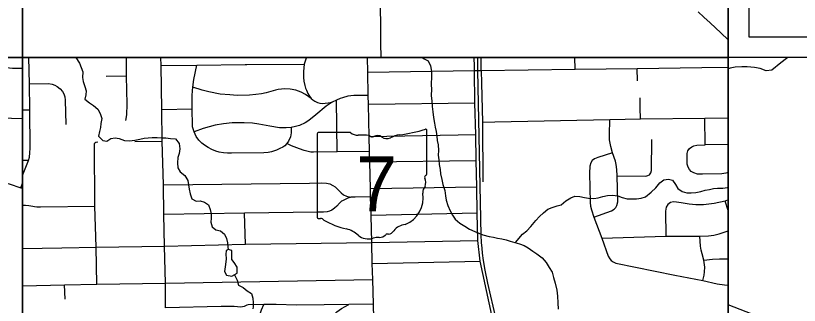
# Model space of a CAD drawing. Extents: x 25.6 to 80.6, y 0.2 to 24.5.
# Drawn here: x 40.98 to 44.756, y 16.537 to 17.932 of the extents above; entities that cross this region are included whole.
import ezdxf

# ---------------------------------------------------------------- set-up
doc = ezdxf.new("R2010")
doc.units = 0
for name, color, linetype in [('GM_X_County_Road', 7, 'Continuous'), ('GM_X_Minor_Lake', 7, 'Continuous'), ('GM_X_Minor_River', 7, 'Continuous'), ('GM_X_Rail_Line', 7, 'Continuous'), ('GM_X_State_Route', 7, 'Continuous'), ('GM_X_State_Shield', 7, 'Continuous'), ('GM_X_Township_Road', 7, 'Continuous'), ('SH_Data', 7, 'Continuous'), ('SH_Text', 7, 'Continuous')]:
    doc.layers.add(name, color=color, linetype=linetype)

msp = doc.modelspace()

# ---------------------------------------------------------------- linework, layer by layer
at = {"layer": 'GM_X_County_Road'}
for p, q in [((43.19, 17.6872), (43.1891, 17.7303)), ((43.223, 17.6682), (43.2221, 17.7303)), ((43.223, 17.6682), (43.2245, 17.6061)), ((41.702, 16.5259), (41.7012, 16.6437))]:
    msp.add_line(p, q, dxfattribs=at)
for points in [[(41.0128, 17.1618), (41.0327, 17.2096), (41.0418, 17.2352), (41.0459, 17.2505), (41.0486, 17.2706), (41.0503, 17.2942), (41.048, 17.4781), (41.0465, 17.6038), (41.0441, 17.7303)], [(41.7012, 16.6437), (41.6971, 16.8224), (41.6944, 16.9752), (41.6922, 17.1167), (41.6865, 17.3277), (41.685, 17.4787), (41.681, 17.6918), (41.6801, 17.7303)], [(43.4744, 15.6231), (43.4157, 15.8771), (43.3295, 16.2378), (43.2913, 16.4079), (43.2182, 16.7492), (43.2068, 16.8496), (43.2038, 16.9808), (43.2018, 17.1076), (43.1983, 17.2332), (43.1967, 17.3603), (43.1924, 17.511), (43.1904, 17.6677), (43.19, 17.6872)], [(43.2245, 17.6061), (43.2289, 17.4196), (43.2882, 17.4207)], [(43.2882, 17.4207), (43.842, 17.4314), (43.991, 17.4346), (44.3, 17.4385), (44.4128, 17.4405)]]:
    msp.add_lwpolyline(points, dxfattribs=at)
at = {"layer": 'GM_X_Minor_Lake'}
for points in [[(42.0209, 16.8011), (42.0034, 16.8054), (41.9936, 16.7992), (41.9931, 16.784), (41.995, 16.7605), (41.9916, 16.7331), (41.986, 16.7004), (41.9961, 16.6823), (42.0212, 16.6781), (42.0468, 16.6914), (42.0479, 16.7202), (42.0331, 16.7428), (42.0208, 16.7571)], [(42.0208, 16.7571), (42.0209, 16.8011)]]:
    msp.add_lwpolyline(points, dxfattribs=at)
at = {"layer": 'GM_X_Minor_River'}
for points in [[(41.2693, 17.7303), (41.2696, 17.7298), (41.2874, 17.7028), (41.296, 17.6824), (41.3039, 17.6605), (41.3021, 17.6339), (41.3054, 17.6142), (41.3126, 17.59), (41.319, 17.5696), (41.3177, 17.5506), (41.3128, 17.5292), (41.335, 17.5113), (41.3549, 17.4987), (41.3764, 17.4808), (41.3865, 17.4604), (41.3945, 17.437), (41.3903, 17.4119), (41.3891, 17.3929), (41.3841, 17.3738), (41.3799, 17.3517), (41.3999, 17.3315), (41.4196, 17.3272), (41.4391, 17.3404), (41.4588, 17.3437), (41.4793, 17.341), (41.5037, 17.3299), (41.528, 17.3288), (41.5537, 17.3322), (41.5778, 17.3378), (41.599, 17.3427), (41.6187, 17.3429), (41.6383, 17.3447), (41.6611, 17.3458), (41.6823, 17.3431), (41.7028, 17.3441), (41.7255, 17.3407), (41.7498, 17.338), (41.7683, 17.3162), (41.7702, 17.2912), (41.7676, 17.2676), (41.7618, 17.2485), (41.7599, 17.2227), (41.7618, 17.1999), (41.7727, 17.1796), (41.7957, 17.1624), (41.8089, 17.1383), (41.813, 17.1171), (41.8164, 17.0959), (41.8205, 17.0732), (41.8284, 17.0498), (41.8491, 17.0379), (41.8695, 17.0397), (41.8893, 17.0331), (41.9092, 17.0213), (41.9171, 16.9986), (41.922, 16.9782), (41.9215, 16.9561), (41.9211, 16.9371), (41.926, 16.9152), (41.9451, 16.901), (41.9664, 16.896), (41.9863, 16.8804), (41.9958, 16.8585), (42.0006, 16.838), (42.0017, 16.8175), (42.0038, 16.8053)], [(42.9386, 17.7303), (42.948, 17.7246), (42.967, 17.715), (42.978, 17.6894), (42.983, 17.6636), (42.9833, 17.6408), (42.9825, 17.5983), (42.9828, 17.5778), (42.9817, 17.5466), (42.9844, 17.5194), (42.9871, 17.4943), (42.9897, 17.4685), (42.9939, 17.4413), (42.9974, 17.4147), (43.0007, 17.3943), (43.0063, 17.3746), (43.0089, 17.3511), (43.0115, 17.3299), (43.0149, 17.3094), (43.0168, 17.2829), (43.0164, 17.2608), (43.019, 17.2381), (43.0208, 17.2153), (43.025, 17.1903), (43.0268, 17.1706), (43.0333, 17.1434), (43.0382, 17.1191), (43.0477, 17.0904), (43.0504, 17.0646), (43.0545, 17.0427), (43.0625, 17.017), (43.0727, 16.992), (43.0844, 16.9709), (43.0983, 16.9514), (43.1206, 16.9335), (43.1443, 16.9179), (43.1672, 16.9037), (43.1916, 16.8927), (43.2313, 16.8765), (43.2617, 16.8686), (43.2815, 16.8651), (43.302, 16.8601), (43.3225, 16.8566), (43.343, 16.8523), (43.3628, 16.8465), (43.3856, 16.84), (43.407, 16.8327), (43.4306, 16.8246), (43.4497, 16.8135), (43.4719, 16.7986), (43.491, 16.7845), (43.5171, 16.7666), (43.5356, 16.7426), (43.5511, 16.7192), (43.5651, 16.6974), (43.5715, 16.6717), (43.5788, 16.6437), (43.5876, 16.6096), (43.5903, 16.5808), (43.5916, 16.5497), (43.5935, 16.5186)], [(44.7004, 17.7303), (44.6933, 17.7249), (44.667, 17.704)], [(44.667, 17.704), (44.6235, 17.67), (44.5955, 17.6667), (44.5673, 17.677), (44.5399, 17.6821), (44.5042, 17.6855), (44.4784, 17.6852), (44.4465, 17.6834), (44.423, 17.6793), (44.4128, 17.675)], [(43.3887, 16.8389), (43.4222, 16.88), (43.4424, 16.8954), (43.4618, 16.9162), (43.4856, 16.9454), (43.5042, 16.9654), (43.5237, 16.9831), (43.5446, 16.9994), (43.5657, 17.0088), (43.5891, 17.0159), (43.6087, 17.0215), (43.6311, 17.0401), (43.6544, 17.0541), (43.674, 17.0627), (43.699, 17.0608), (43.7203, 17.0557), (43.74, 17.053), (43.7651, 17.051), (43.787, 17.0544), (43.8096, 17.0608), (43.8323, 17.0664), (43.855, 17.0675), (43.8808, 17.064), (43.9014, 17.0567), (43.9265, 17.0502), (43.95, 17.0506), (43.9719, 17.0501), (43.9939, 17.0535), (44.015, 17.0598), (44.0427, 17.0815), (44.0643, 17.103), (44.0829, 17.1276), (44.1024, 17.1408), (44.1258, 17.1449), (44.1448, 17.1399), (44.1588, 17.1195), (44.1697, 17.0999), (44.1919, 17.0851), (44.214, 17.0793), (44.2344, 17.0781), (44.2579, 17.0807), (44.2805, 17.0855), (44.3024, 17.0919), (44.3228, 17.0952), (44.3425, 17.0993), (44.3621, 17.1019), (44.3871, 17.1014), (44.4098, 17.1048), (44.4128, 17.1059)], [(42.0339, 16.6847), (42.0465, 16.6587), (42.0537, 16.6345), (42.0758, 16.6234), (42.095, 16.6077), (42.1157, 16.5936), (42.1221, 16.5724), (42.1239, 16.5497), (42.1242, 16.5307), (42.1235, 16.5202)]]:
    msp.add_lwpolyline(points, dxfattribs=at)
at = {"layer": 'GM_X_Rail_Line'}
for points in [[(43.2951, 16.4705), (43.2554, 16.6435), (43.2415, 16.7067), (43.2337, 16.7535), (43.2295, 16.7885), (43.2269, 16.8128), (43.2251, 16.8392), (43.2235, 16.875), (43.2073, 17.6679), (43.2061, 17.7303)], [(47.8128, 15.8191), (47.6057, 15.8302), (47.3402, 15.8521), (47.1631, 15.8871), (46.9912, 15.9223), (46.7273, 15.9853), (45.9383, 16.1769), (45.6136, 16.2567), (45.5036, 16.2842), (45.3992, 16.2924), (45.0499, 16.3176), (44.9789, 16.3252), (44.6728, 16.4383), (44.4128, 16.5397)]]:
    msp.add_lwpolyline(points, dxfattribs=at)
at = {"layer": 'GM_X_State_Route'}
for points in [[(42.7406, 17.7303), (42.7405, 17.7348), (42.7396, 17.7946), (42.7387, 17.8812), (42.7378, 17.976), (42.7363, 18.0903), (42.7345, 18.1848), (42.7325, 18.3068), (42.7307, 18.3811), (42.7294, 18.4657), (42.7275, 18.534), (42.7248, 18.6943), (42.7233, 18.8161), (42.7222, 18.8744), (42.7208, 18.9664), (42.7195, 19.0521), (42.7188, 19.0882), (42.7177, 19.1628), (42.716, 19.2796), (42.7133, 19.4075), (42.7128, 19.4303)], [(44.2691, 17.9501), (44.2962, 17.9245), (44.3264, 17.8967), (44.377, 17.8489), (44.4128, 17.815)], [(42.707, 16.4054), (42.7033, 16.5436), (42.7004, 16.6623), (42.6982, 16.7393), (42.696, 16.8392), (42.6925, 16.9703), (42.69, 17.0594), (42.69, 17.1003), (42.6863, 17.2266), (42.6854, 17.2779), (42.6831, 17.3503), (42.6794, 17.5033), (42.6785, 17.5479), (42.6774, 17.6597), (42.6758, 17.7303)]]:
    msp.add_lwpolyline(points, dxfattribs=at)
at = {"layer": 'GM_X_State_Shield'}
for p, q in [((42.5929, 17.3692), (42.4384, 17.3692)), ((42.9606, 17.1697), (42.9606, 17.3791)), ((42.4332, 17.3623), (42.4332, 16.962)), ((42.9605, 17.1698), (42.9606, 17.1697))]:
    msp.add_line(p, q, dxfattribs=at)
for centre, radius, start, end in [((42.4393, 17.3631), 0.00611, 98.1301, 188.1301), ((42.6296, 17.4156), 0.0593, 231.6195, 271.1119), ((42.7727, 17.9148), 0.5592, 275.8445, 288.9065), ((42.9547, 17.3799), 0.00587, 351.8621, 97.738), ((42.6493, 17.1445), 0.2127, 80.4867, 94.9883), ((42.6976, 17.3652), 0.0171, 219.7921, 297.1024), ((42.7227, 17.3189), 0.0355, 54.4667, 119.1411), ((42.7685, 17.3824), 0.0428, 233.8562, 294.8282), ((42.8441, 17.2469), 0.1125, 97.3462, 120.7689), ((42.9592, 17.1543), 0.00909, 107.944, 210.337), ((42.9014, 17.1279), 0.0545, 340.033, 23.6496), ((42.9543, 17.1689), 0.00628, 289.6038, 7.7341), ((42.9816, 17.0821), 0.0397, 136.8065, 186.9296), ((42.8041, 17.0554), 0.1399, 292.3089, 8.9858), ((42.4393, 16.9611), 0.00616, 171.9584, 258.3066), ((42.4403, 17.0021), 0.047, 267.339, 280.6039), ((42.4499, 16.9389), 0.017, 29.7484, 93.2717), ((42.664, 17.2985), 0.4038, 240.4129, 257.1985), ((42.863, 16.8497), 0.0766, 94.4031, 142.5768), ((42.5436, 16.7822), 0.1264, 47.1842, 75.836), ((42.7711, 16.8682), 0.012, 65.7517, 132.6484), ((42.766, 16.9232), 0.0452, 282.8732, 323.2771), ((42.6803, 16.9369), 0.0802, 230.7004, 286.2918), ((42.7266, 16.7986), 0.0659, 85.6951, 111.2099), ((42.7325, 16.907), 0.0427, 268.777, 315.5493)]:
    msp.add_arc(centre, radius, start, end, dxfattribs=at)
at = {"layer": 'GM_X_Township_Road'}
for p, q in [((43.6758, 17.6744), (43.6747, 17.7303)), ((42.0938, 17.6968), (42.3702, 17.6981)), ((43.9768, 17.6184), (43.975, 17.677)), ((41.512, 17.6403), (41.4165, 17.6391)), ((42.6774, 17.6597), (43.1904, 17.6677)), ((43.1904, 17.6677), (43.223, 17.6682)), ((42.529, 17.2759), (42.5257, 17.5253)), ((41.8303, 17.4819), (41.685, 17.4787)), ((43.1924, 17.511), (42.6794, 17.5033)), ((41.0128, 17.4776), (41.048, 17.4781)), ((40.9067, 17.44), (41.0128, 17.4372)), ((43.2289, 17.4196), (43.2301, 17.1323)), ((44.3013, 17.3102), (44.3, 17.4385)), ((42.6831, 17.3503), (43.1967, 17.3603)), ((41.5543, 17.3252), (41.6865, 17.3277)), ((44.4128, 17.311), (44.3013, 17.3102)), ((41.0418, 17.2352), (41.0128, 17.2349)), ((43.1983, 17.2332), (42.6863, 17.2266)), ((41.0055, 17.1036), (41.0128, 17.1251)), ((41.6922, 17.1167), (42.3952, 17.1255)), ((42.69, 17.1003), (43.2018, 17.1076)), ((44.4128, 16.9944), (44.3983, 17.0393)), ((42.0866, 16.8309), (42.0826, 16.9803)), ((43.2038, 16.9808), (42.6925, 16.9703)), ((42.696, 16.8392), (43.2068, 16.8496)), ((41.0128, 16.8105), (41.2022, 16.8138)), ((42.6982, 16.7393), (43.2182, 16.7492)), ((41.0128, 16.6999), (41.0124, 16.6988)), ((41.218, 16.5664), (41.2157, 16.6354))]:
    msp.add_line(p, q, dxfattribs=at)
for points in [[(41.5127, 17.7303), (41.512, 17.7253), (41.512, 17.6403), (41.515, 17.5061), (41.5133, 17.455), (41.5097, 17.4275)], [(42.3808, 17.7303), (42.3779, 17.7216), (42.3702, 17.6981), (42.3661, 17.6625), (42.3672, 17.6335), (42.3686, 17.6168), (42.3729, 17.5958), (42.3769, 17.5825), (42.3806, 17.5737), (42.3879, 17.5572), (42.3959, 17.5435), (42.4039, 17.5334), (42.4116, 17.5265), (42.4213, 17.5194), (42.4338, 17.5133), (42.4448, 17.5105), (42.4585, 17.5093), (42.4719, 17.5103), (42.4863, 17.5123), (42.5043, 17.516)], [(40.892, 17.6871), (40.964, 17.6791), (41.0128, 17.6793)], [(41.681, 17.6918), (41.8526, 17.6932), (42.0859, 17.6968), (42.0938, 17.6968)], [(42.2365, 17.2848), (42.2272, 17.2808), (42.2127, 17.2765), (42.1965, 17.2735), (42.1759, 17.2714), (42.0193, 17.2696), (42.0003, 17.2702), (41.9811, 17.2714), (41.9609, 17.2743), (41.9443, 17.2787), (41.9246, 17.287), (41.9072, 17.2962), (41.8892, 17.3075), (41.8762, 17.3177), (41.8621, 17.3325), (41.8494, 17.3506), (41.8401, 17.3731), (41.8354, 17.3863), (41.8325, 17.3958), (41.8316, 17.4043), (41.8303, 17.4819), (41.8307, 17.5468), (41.8322, 17.5703), (41.8333, 17.587), (41.838, 17.6245), (41.8526, 17.6932)], [(43.223, 17.6682), (43.6758, 17.6744), (43.975, 17.677), (44.286, 17.6817), (44.4128, 17.6835)], [(41.0465, 17.6038), (41.138, 17.6043), (41.1551, 17.602), (41.1683, 17.5974), (41.1803, 17.5907), (41.1942, 17.5798), (41.205, 17.5673), (41.2115, 17.5548), (41.2168, 17.5403), (41.2191, 17.5255), (41.221, 17.4083)], [(42.4039, 17.5334), (42.3762, 17.552), (42.3561, 17.5627), (42.3298, 17.5725), (42.3031, 17.5777), (42.2775, 17.579), (42.2608, 17.5784), (42.2455, 17.5764), (42.2315, 17.5731), (42.2089, 17.5658), (42.1865, 17.5602), (42.1642, 17.555), (42.137, 17.5514), (42.106, 17.549), (42.0466, 17.5481), (42.0123, 17.55), (41.966, 17.5545), (41.9112, 17.5644), (41.8782, 17.5735), (41.8333, 17.587)], [(42.6785, 17.5479), (42.6086, 17.5471), (42.5811, 17.5437), (42.5546, 17.5369), (42.543, 17.5327), (42.5257, 17.5253), (42.5043, 17.516), (42.4899, 17.506)], [(43.991, 17.4346), (43.9884, 17.4886), (43.9895, 17.5364)], [(42.4899, 17.506), (42.4755, 17.496), (42.4258, 17.455), (42.3922, 17.4277), (42.3745, 17.4157), (42.3468, 17.4031), (42.3282, 17.3974), (42.3077, 17.3929), (42.2828, 17.3909), (42.2506, 17.3921), (42.2042, 17.3998), (42.1522, 17.41), (42.1215, 17.4141), (42.0813, 17.4163), (42.0237, 17.4153), (41.9817, 17.4114), (41.9412, 17.4045), (41.8829, 17.388), (41.8401, 17.3731)], [(43.7656, 16.9615), (43.85, 16.9922), (43.8631, 16.9997), (43.8712, 17.0084), (43.8772, 17.0178), (43.8806, 17.0353), (43.8779, 17.16), (43.8769, 17.191), (43.8737, 17.2144), (43.8694, 17.2307), (43.8551, 17.2707), (43.8468, 17.3022), (43.8417, 17.3339), (43.8417, 17.3582), (43.842, 17.4314)], [(42.3077, 17.3929), (42.3069, 17.3681), (42.3036, 17.3489), (42.295, 17.3274), (42.2871, 17.3155), (42.2764, 17.305), (42.268, 17.2992), (42.2533, 17.2918), (42.2365, 17.2848)], [(43.8779, 17.16), (44.0161, 17.1594), (44.0264, 17.1617), (44.0344, 17.1662), (44.0407, 17.1745), (44.0441, 17.1865), (44.045, 17.3354)], [(41.3704, 16.6393), (41.3682, 16.8168), (41.3621, 17.0145), (41.3596, 17.316), (41.3613, 17.3201), (41.3662, 17.3233), (41.3762, 17.3245)], [(42.6854, 17.2779), (42.529, 17.2759), (42.4148, 17.2742), (42.4015, 17.2753), (42.3828, 17.2792), (42.3701, 17.2828), (42.3478, 17.2898), (42.309, 17.3053), (42.2871, 17.3155)], [(44.4128, 17.1767), (44.4023, 17.1738), (44.3826, 17.1704), (44.2891, 17.1679), (44.265, 17.1682), (44.2471, 17.1743), (44.2347, 17.1822), (44.2263, 17.1914), (44.2202, 17.2018), (44.2157, 17.2163), (44.2153, 17.268), (44.2193, 17.2804), (44.2261, 17.2921), (44.2374, 17.301), (44.248, 17.3057), (44.2627, 17.3089), (44.3013, 17.3102)], [(43.8551, 17.2707), (43.7842, 17.2482), (43.7696, 17.2422), (43.7582, 17.2339), (43.7513, 17.2233), (43.7468, 17.207), (43.7453, 17.1741), (43.7486, 17.032), (43.7503, 17.0148), (43.7541, 16.9972), (43.7656, 16.9615), (43.8047, 16.8604), (43.8347, 16.7731), (43.8421, 16.7609), (43.849, 16.7526), (43.8589, 16.746), (43.8724, 16.7405), (44.1556, 16.6829), (44.2907, 16.6562), (44.3596, 16.6413), (44.395, 16.6357), (44.4128, 16.6339)], [(39.8547, 17.2112), (39.8666, 17.1932), (39.9331, 17.1796), (40.0798, 17.1537), (40.1385, 17.1475), (40.2033, 17.1464), (40.4013, 17.1396), (40.5305, 17.1362), (40.5559, 17.1345), (40.5812, 17.1294), (40.6032, 17.1238), (40.6935, 17.1204), (40.7155, 17.1215), (40.7538, 17.1193), (40.7753, 17.1199), (40.7916, 17.1244), (40.8085, 17.1311), (40.8255, 17.1334), (40.8954, 17.1306), (40.9185, 17.1294), (40.9491, 17.1225), (41.0055, 17.1036), (41.0128, 17.101)], [(42.3952, 17.1255), (42.4514, 17.1262), (42.4784, 17.1252), (42.494, 17.1214), (42.5079, 17.1143), (42.519, 17.1072), (42.5315, 17.0945), (42.5485, 17.0781), (42.56, 17.0691), (42.5746, 17.063), (42.5946, 17.0586)], [(42.5542, 17.0402), (42.5506, 17.0383), (42.5408, 17.0294), (42.5274, 17.015), (42.5167, 17.0045), (42.5031, 16.9958), (42.4915, 16.991), (42.4806, 16.9878), (42.4635, 16.9859), (42.4349, 16.9853), (42.0826, 16.9803), (41.6944, 16.9752)], [(42.69, 17.0594), (42.6157, 17.0578), (42.5946, 17.0586), (42.5798, 17.0536), (42.5542, 17.0402)], [(44.4128, 17.0447), (44.3983, 17.0393), (44.3457, 17.0273), (44.2936, 17.0207), (44.2579, 17.0204), (44.2256, 17.0241), (44.1864, 17.0301), (44.1635, 17.0344), (44.1495, 17.0356), (44.1346, 17.0321), (44.1215, 17.023), (44.1135, 17.009), (44.1109, 16.9912), (44.1118, 16.8694)], [(41.0128, 17.0198), (41.0269, 17.0198), (41.0441, 17.0181), (41.0625, 17.014), (41.0712, 17.0124), (41.0823, 17.012), (41.1003, 17.0117), (41.3621, 17.0145)], [(43.8047, 16.8604), (44.1118, 16.8694), (44.2756, 16.8694), (44.3188, 16.8717), (44.3442, 16.8754), (44.3688, 16.8814), (44.4128, 16.8959)], [(44.2907, 16.6562), (44.2966, 16.682), (44.2989, 16.6992), (44.2997, 16.7213), (44.296, 16.7541), (44.2874, 16.7857), (44.2826, 16.8023), (44.2792, 16.8222), (44.2756, 16.8694)], [(41.2022, 16.8138), (41.3682, 16.8168), (41.6971, 16.8224)], [(41.6971, 16.8224), (42.0866, 16.8309), (42.696, 16.8392)], [(44.296, 16.7541), (44.3367, 16.7591), (44.3715, 16.7611), (44.412, 16.7608), (44.4128, 16.7609)], [(41.0128, 16.6315), (41.2157, 16.6354), (41.3704, 16.6393), (41.7012, 16.6437), (42.7004, 16.6623)], [(42.4666, 16.5399), (42.3324, 16.5384), (42.2355, 16.5414), (42.1764, 16.5406), (42.1005, 16.5399), (42.0944, 16.5385), (42.0878, 16.5355), (42.0808, 16.5319), (42.0729, 16.5296), (42.0649, 16.5287), (42.0321, 16.5321), (41.9704, 16.5317), (41.702, 16.5259)], [(42.201, 16.396), (42.1846, 16.4073), (42.1745, 16.4162), (42.1692, 16.4249), (42.159, 16.4562), (42.1571, 16.4721), (42.1581, 16.4876), (42.1599, 16.5009), (42.1649, 16.5158), (42.1764, 16.5406)], [(42.2836, 16.1309), (42.2862, 16.1583), (42.29, 16.1781), (42.2986, 16.2052), (42.3156, 16.235), (42.3389, 16.2649), (42.347, 16.2752), (42.4409, 16.4002), (42.495, 16.4698), (42.5125, 16.4919), (42.5267, 16.5065), (42.5505, 16.5222), (42.585, 16.5412)], [(42.7033, 16.5436), (42.585, 16.5412), (42.4666, 16.5399)]]:
    msp.add_lwpolyline(points, dxfattribs=at)
at = {"layer": 'SH_Data'}
for p, q in [((44.5128, 21.2303), (44.5128, 17.8303)), ((41.0128, 21.1303), (41.0128, 14.3303)), ((44.4128, 21.1303), (44.4128, 14.3303)), ((44.5128, 17.8303), (47.9128, 17.8303)), ((41.0128, 17.7303), (41.0128, 17.7303))]:
    msp.add_line(p, q, dxfattribs=at)
at = {"layer": 'SH_Text'}
for points in [[(37.6128, 21.1303), (44.4128, 21.1303), (44.4128, 14.3303), (37.6128, 14.3303)], [(37.6128, 21.1303), (44.4128, 21.1303), (44.4128, 14.3303), (37.6128, 14.3303)], [(37.6128, 17.7303), (41.0128, 17.7303), (41.0128, 21.1303), (37.6128, 21.1303)], [(37.6128, 17.7303), (41.0128, 17.7303), (41.0128, 21.1303), (37.6128, 21.1303)], [(41.0128, 17.7303), (44.4128, 17.7303), (44.4128, 21.1303), (41.0128, 21.1303)], [(41.0128, 17.7303), (44.4128, 17.7303), (44.4128, 21.1303), (41.0128, 21.1303)], [(37.6128, 14.3303), (41.0128, 14.3303), (41.0128, 17.7303), (37.6128, 17.7303)], [(37.6128, 14.3303), (41.0128, 14.3303), (41.0128, 17.7303), (37.6128, 17.7303)], [(41.0128, 14.3303), (44.4128, 14.3303), (44.4128, 17.7303), (41.0128, 17.7303)], [(41.0128, 14.3303), (44.4128, 14.3303), (44.4128, 17.7303), (41.0128, 17.7303)], [(44.4128, 14.3303), (47.8128, 14.3303), (47.8128, 17.7303), (44.4128, 17.7303)]]:
    msp.add_lwpolyline(points, close=True, dxfattribs=at)

# ---------------------------------------------------------------- texts
at = {"layer": 'GM_X_State_Shield'}
msp.add_text('7', height=0.2637, dxfattribs=at).set_placement((42.6214, 16.9902))

doc.saveas('drawing.dxf')
